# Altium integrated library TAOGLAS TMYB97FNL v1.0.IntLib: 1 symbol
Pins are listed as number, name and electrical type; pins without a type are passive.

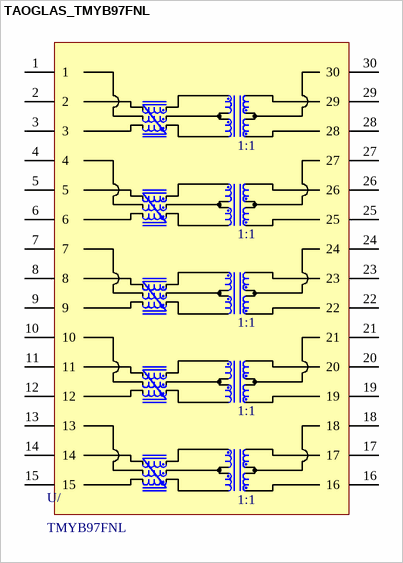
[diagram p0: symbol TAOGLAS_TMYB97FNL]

## TAOGLAS_TMYB97FNL
designator U/, comment TMYB97FNL
10G Base-T transformer Single Port and 30pin SMT with PoE Ultra; ComponentLibStatus: Created; MFG: Taoglas; Temp_High: +85C; Temp_Low: -40C
footprint TAOGLAS_TMYB97FNL (10G Base-T transformer Single Port and 30pin SMT with PoE Ultra)
pins: 1, 2, 3, 4, 5, 6, 7, 8, 9, 10, 11, 12, 13, 14, 15, 16, 17, 18, 19, 20, 21, 22, 23, 24, 25, 26, 27, 28, 29, 30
